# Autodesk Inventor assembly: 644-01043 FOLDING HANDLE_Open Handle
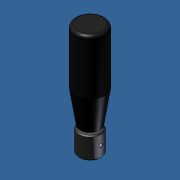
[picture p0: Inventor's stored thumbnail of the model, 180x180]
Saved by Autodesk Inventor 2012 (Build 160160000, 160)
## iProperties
Created: 2013-10
Part Number: 644-01043 FOLDING HANDLE_Open Handle
Document SubType Name: Assembly
Designer: Admin
Author: Admin
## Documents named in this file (3)
- C:\Andys Backup Data\ANDY'S INVENTOR\INVENTOR LIBRARIES\PARTS LIBRARY\HYDRAULIC VERTICAL ADJUSTMENT\27.9001Telescoping Twin Leg System\SUBCOMPONENTS\Qxx18_crank pump\644-01043 FOLDING HANDLE_Open Handle.iam
- C:\Andys Backup Data\ANDY'S INVENTOR\INVENTOR LIBRARIES\PARTS LIBRARY\HYDRAULIC VERTICAL ADJUSTMENT\27.9001Telescoping Twin Leg System\SUBCOMPONENTS\Qxx18_crank pump\Sankq_Base_20x20.iam
- C:\Andys Backup Data\ANDY'S INVENTOR\INVENTOR LIBRARIES\PARTS LIBRARY\HYDRAULIC VERTICAL ADJUSTMENT\27.9001Telescoping Twin Leg System\SUBCOMPONENTS\Qxx18_crank pump\Sankq_7011P566_Handle.iam
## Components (2 placed, 2 different names)
1. Sankq_Base_20x20:1 [sub-assembly]
2. Sankq_7011P566_Handle:1 [sub-assembly]
